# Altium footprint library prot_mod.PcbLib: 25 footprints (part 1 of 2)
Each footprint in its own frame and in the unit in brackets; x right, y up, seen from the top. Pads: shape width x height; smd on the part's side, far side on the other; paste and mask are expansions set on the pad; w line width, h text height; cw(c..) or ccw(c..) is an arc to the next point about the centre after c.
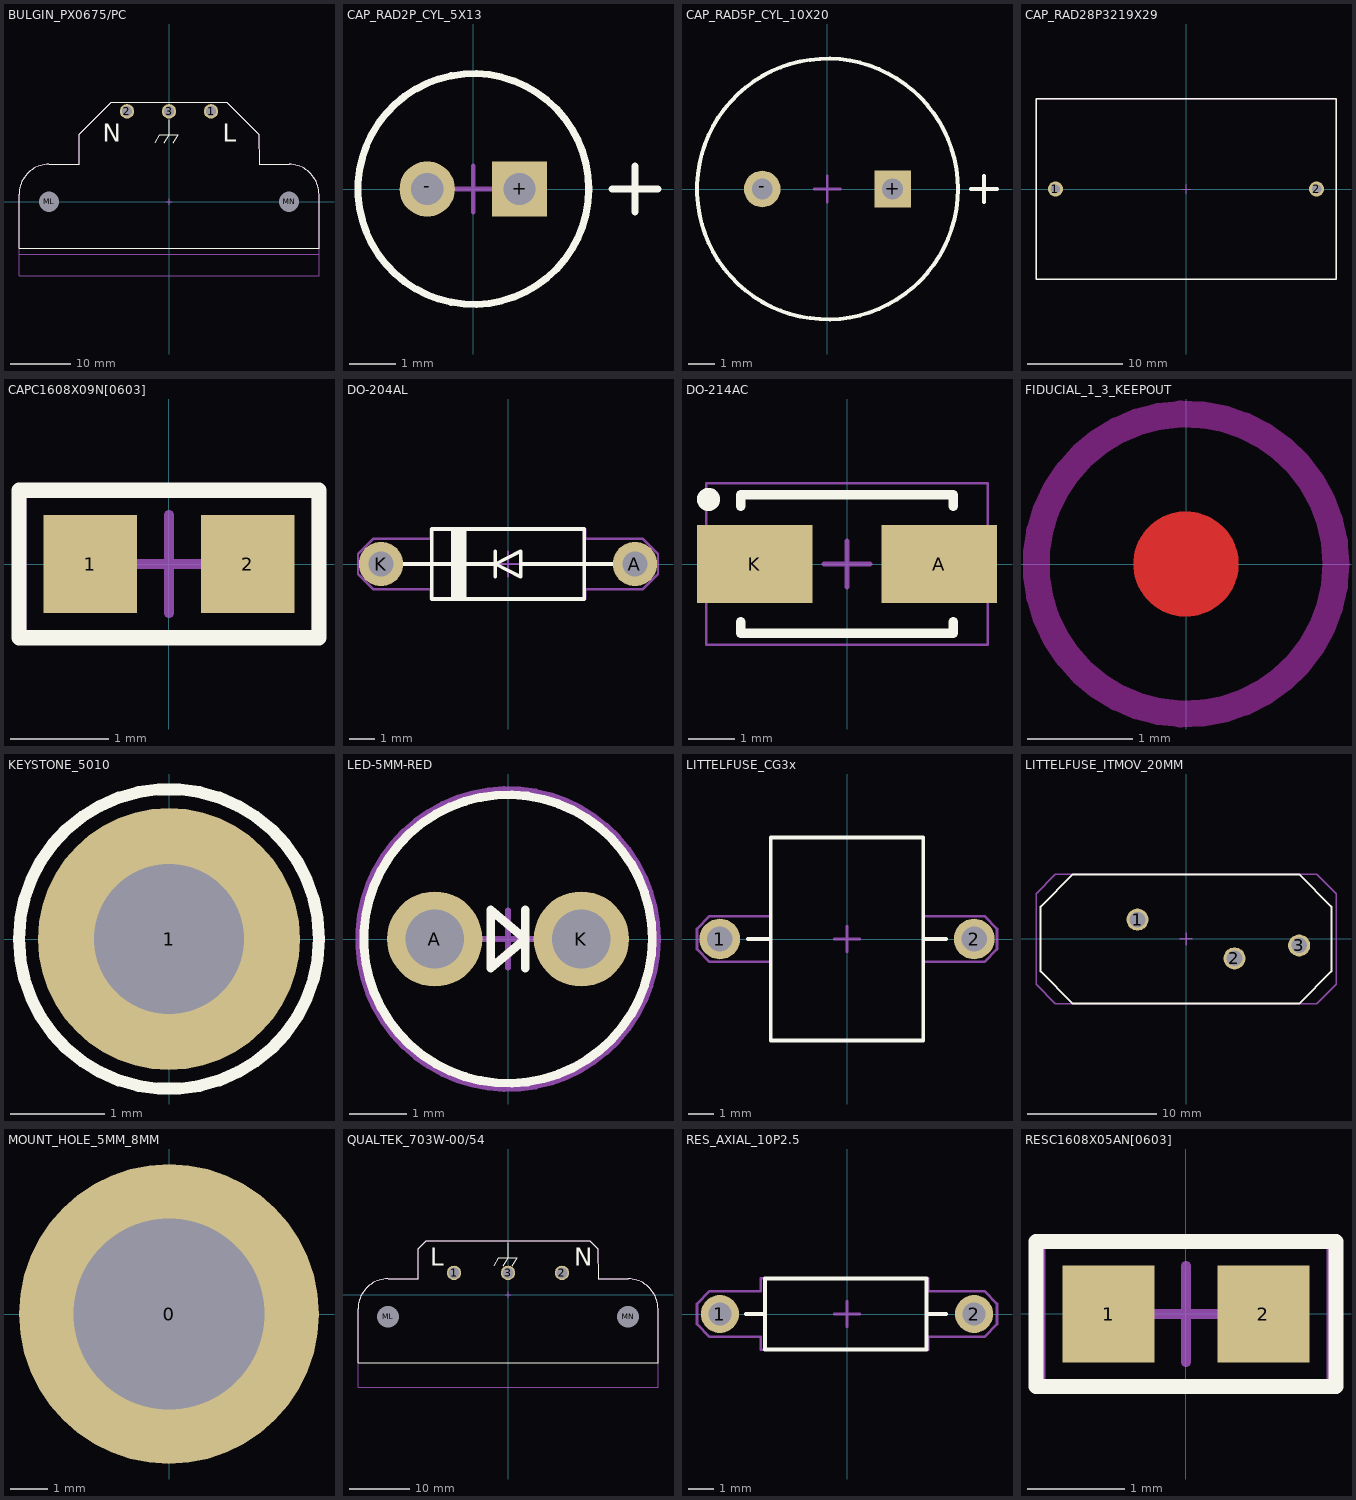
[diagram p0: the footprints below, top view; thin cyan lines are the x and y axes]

## BULGIN_PX0675/PC [mm]
pads (5):
  round 2.4 hole 1.7: 1(7,15.1) 2(-7,15.1) 3(0,15.1)
  round 2 hole 3.4 unplated: ML(-20,0) MN(20,0)
Top Overlay:
  lines w0.153: -2.306,9.853 -1.508,11.15 0,11.15 ; -0.8,9.85 0,11.15 ; 0,13.65 0,11.15 ; 0.722,9.836 1.531,11.15 0,11.15 ; -25,-7.75 25,-7.75 25,1.25 ccw(c20,1.25) 20,6.25 15,6.25 15,11.25 9.65,16.6 -9.65,16.6 -15,11.25 -15,6.25 -20,6.25 ccw(c-20,1.25) -25,1.25 -25,-7.75
  text "N" at -11,10 h3
  text "L" at 9,10 h3
Top Component Center:
  lines w0.1: -0.5,0 0.5,0 ; 0,-0.5 0,0.5
Top Courtyard:
  lines w0.1: -25,-12.3 25,-12.3 25,1.25 ccw(c20,1.25) 20,6.25 15,6.25 15,11.25 9.65,16.6 -9.65,16.6 -15,11.25 -15,6.25 -20,6.25 ccw(c-20,1.25) -25,1.25 -25,-12.3
  lines w0.127: -25,-8.7 25,-8.7
3D body "px0675-pc.stp": height 30.2, standoff -3.8, extent -24.936,-12.251 24.864,25.786

## CAP_RAD2P_CYL_5X13 [mm]
pads (2):
  rect 1.2x1.2 hole 0.7: +(1,0)
  round 1.2 hole 0.7: -(-1,0)
Top Overlay:
  circle w0.153: c0,0 r2.5
  lines w0.153: 3,0 4,0 ; 3.5,-0.5 3.5,0.5
Top Component Center:
  lines w0.1: -0.5,0 0.5,0 ; 0,-0.5 0,0.5
Top Courtyard:
  circle w0.1: c0,0 r2.5
3D body "Kemet_RB2x5x12_5_ESH226M035AC3AA.step": height 12.5, standoff -5, extent -2.745,-2.75 2.745,2.75

## CAP_RAD5P_CYL_10X20 [mm]
pads (2):
  rect 1.4x1.4 hole 0.8: +(2.5,0)
  round 1.4 hole 0.8: -(-2.5,0)
Top Overlay:
  circle w0.153: c0,0 r5
  lines w0.153: 5.5,0 6.5,0 ; 6,-0.5 6,0.5
Top Component Center:
  lines w0.1: -0.5,0 0.5,0 ; 0,-0.5 0,0.5
Top Courtyard:
  circle w0.1: c0,0 r5
3D body "Kemet_ESH687M035AH4AA.step": height 22, standoff -5, extent -5.25,-5.225 5.25,5.275

## CAP_RAD28P3219X29 [mm]
pads (2):
  round 1.6 hole 1: 1(-13.75,0) 2(13.75,0)
Top Overlay:
  lines w0.153: -15.8,-9.5 15.8,-9.5 15.8,9.5 -15.8,9.5 -15.8,-9.5
Top Component Center:
  lines w0.1: -0.5,0 0.5,0 ; 0,-0.5 0,0.5
Top Courtyard:
  lines w0.1: -15.8,-9.5 -15.8,9.5 15.8,9.5 15.8,-9.5 -15.8,-9.5
3D body "Kemet_PHE845VF6330MR06L2.step": height 29.05, standoff -4.95, extent -15.75,-9.501 15.75,9.5

## CAPC1608X09N[0603] [mm]
pads (2):
  rect 0.95x1 smd: 1(-0.8,0) 2(0.8,0)
Top Overlay:
  lines w0.153: -1.525,-0.75 1.525,-0.75 1.525,0.75 -1.525,0.75 -1.525,0 -1.525,-0.75
Top Component Center:
  lines w0.1: -0.5,0 0.5,0 ; 0,-0.5 0,0.5
Top Courtyard:
  lines w0.1: -1.5,-0.75 -1.5,0.75 1.5,0.75 1.5,-0.75 -1.5,-0.75
3D body: height 0.9, standoff 0, extent -0.55,-0.45 0.55,0.45
3D body: height 0.9, standoff 0, extent -0.85,-0.45 -0.55,0.45
3D body: height 0.9, standoff 0, extent 0.55,-0.45 0.85,0.45

## DO-204AL [mil]
pads (2):
  round 70 hole 40: A(200,0) K(-200,0)
Top Overlay:
  region: -64.97,55.11 -89.97,55.11 -89.97,-54.89 -64.97,-54.89
  lines w6.02: -165,0 -135,0 -80,0 -20,0 ; -20,-20 -20,20 ; 20,0 120,0 ; 135,0 165,0 ; 140,0 120,0 ; -20,0 20,20 20,-20 -20,0 ; 120,0 120,55 -120,55 -120,0 -120,-55 120,-55 120,0
Top Component Center:
  lines w3.94: -19.68,0 19.68,0 ; 0,-19.68 0,19.68
Top Courtyard:
  lines w3.94: -236.22,-15.75 -236.22,0 -236.22,15.75 -212.6,39.37 -122.05,39.37 -122.05,55.12 122.05,55.12 122.05,39.37 212.6,39.37 236.22,15.75 236.22,-15.75 212.6,-39.37 122.05,-39.37 122.05,-55.12 -122.05,-55.12 -122.05,-39.37 -212.6,-39.37 -236.22,-15.75
3D body: height 60, standoff -100, extent 184.06,-15.03 214.06,14.97
3D body: height 75, standoff 45, extent 184.16,-15 214.16,15
3D body: height 75, standoff 45, extent -215.92,-15.06 -185.92,14.94
3D body: height 60, standoff -100, extent -215.94,-15.03 -185.94,14.97
3D body: height 116, standoff 4, extent -94,-56.11 -54,55.89
3D body: height 75, standoff 45, extent -200,-14.97 200,15.03
3D body: height 115, standoff 5, extent -119,-55.11 121,54.89

## DO-214AC [mm]
pads (2):
  rect 2.5x1.7 smd: A(2,0) K(-2,0)
Top Overlay:
  circle w0.25: c-3,1.4 r0.125
  lines w0.2: -2.3,-1.25 -2.3,-1.5 2.3,-1.5 2.3,-1.25 ; -2.3,1.25 -2.3,1.5 2.3,1.5 2.3,1.25
Top Component Center:
  lines w0.1: -0.5,0 0.5,0 ; 0,-0.5 0,0.5
Top Courtyard:
  lines w0.05: -3.05,-1.75 3.05,-1.75 3.05,1.75 -3.05,1.75 -3.05,-1.75
3D body: height 2.4, standoff 0, extent -2.3,-1.46 2.3,1.46
3D body: height 2.4, standoff 2.4, extent -2.3,-1.45 -1.675,1.45

## FIDUCIAL_1_3_KEEPOUT [mm]
Top Layer:
  circle w0.5: c0,0 r0.25
Top Layer keep-out:
  circle w0.254: c0,0 r1.425
Top Solder:
  circle w1.5: c0,0 r0.75

## KEYSTONE_5010 [mil]
pads (1):
  round 110 / inner round 85 / far side round 110 hole 63: 1(0,0)
Top Overlay:
  circle w5: c0,0 r62.99
Top Component Center:
  lines w3.94: -19.68,0 19.68,0 ; 0,-19.68 0,19.68
Top Courtyard:
  circle w3.94: c0,0 r62.99
3D body "keystone-PN5010.STEP": height 319.63, standoff -125, extent -62.05,-62.01 62.04,62.99

## LED-5MM-RED [mil]
pads (2):
  round 65 hole 40: A(-50,0) K(50,0)
Top Overlay:
  circle w6.02: c0,0 r98.43
  lines w6.02: 11.81,-19.68 11.81,19.68 ; -11.81,-19.68 -11.81,19.68 11.81,0 -11.81,-19.68
Top Component Center:
  lines w3.94: -19.68,0 19.68,0 ; 0,-19.68 0,19.68
Top Courtyard:
  circle w3.94: c0,0 r102.36
3D body: height 110, standoff 70, extent -105,-105.21 105,104.79
3D body: height 370, standoff 170, extent -100.04,-100.43 99.96,99.57
3D body: height 270, standoff 70, extent -99.79,-100.2 100.21,99.8
3D body: height 170, standoff 160, extent -5,-5 5,5
3D body: height 160, standoff 150, extent -29,-7 -20,7
3D body: height 60, standoff -120, extent -62.5,-13 -37.5,12
3D body: height 160, standoff 150, extent -15,-33 40,33
3D body: height 150, standoff 50, extent 19,-12.5 62,12.5
3D body: height 150, standoff 50, extent -63,-13 -20,12
3D body: height 50, standoff -120, extent 37,-12.5 62,12.5

## LITTELFUSE_CG3x [mm]
pads (2):
  round 1.6 hole 1: 1(-5,0) 2(5,0)
Top Overlay:
  lines w0.153: -3.9,0 -3,0 ; 3,0 3.9,0 ; -3,0 -3,1.925 -3,4 3,4 3,-4 -3,-4 -3,0
Top Component Center:
  lines w0.1: -0.5,0 0.5,0 ; 0,-0.5 0,0.5
Top Courtyard:
  lines w0.1: -5.9,-0.4 -5.4,-0.9 -3,-0.9 -3,-4 3,-4 3,-0.9 5.4,-0.9 5.9,-0.4 5.9,0.4 5.4,0.9 3,0.9 3,4 -3,4 -3,0.9 -5.4,0.9 -5.9,0.4 -5.9,-0.4
3D body: height 8, standoff 0, extent -2.6,-4 2.6,4
3D body: height 8, standoff 0, extent -3,-4 -2.6,4
3D body: height 8, standoff 0, extent 2.6,-4 3,4
3D body: height 4.4, standoff 3.6, extent -5.2,-0.401 -3,0.399
3D body: height 4.4, standoff 3.6, extent 3,-0.4 5.2,0.4
3D body: height 4.2, standoff -2, extent -5.403,-0.4 -4.603,0.4
3D body: height 4.2, standoff -2, extent 4.6,-0.4 5.4,0.4

## LITTELFUSE_ITMOV_20MM [mm]
pads (3):
  round 1.7 hole 1.2: 1(-3.75,1.5) 2(3.75,-1.5) 3(8.75,-0.5)
Top Overlay:
  lines w0.153: -11.25,-2.5 -8.75,-5 8.75,-5 11.25,-2.5 11.25,2.5 8.75,5 -8.75,5 -11.25,2.5 -11.25,-2.5
Top Component Center:
  lines w0.1: -0.5,0 0.5,0 ; 0,-0.5 0,0.5
Top Courtyard:
  lines w0.1: -11.6,-3.5 -11.6,3.5 -10.1,5 10.1,5 11.6,3.5 11.6,-3.5 10.1,-5 -10.1,-5 -11.6,-3.5
3D body: height 0, standoff -2, extent 8.52,-0.73 8.98,-0.27
3D body: height 0, standoff -2, extent 3.52,-1.73 3.98,-1.27
3D body: height 0, standoff -2, extent -3.98,1.27 -3.52,1.73
3D body: height 9, standoff 0, extent 8.15,-1.1 9.35,0.1
3D body: height 6, standoff 0, extent 3.15,-2.1 4.35,-0.9
3D body: height 6, standoff 0, extent -4.35,0.9 -3.15,2.1
3D body: height 27.5, standoff 4.5, extent -11.5,-3.5 11.5,3.5

## MOUNT_HOLE_5MM_8MM [mm]
pads (1):
  round 8 hole 5.08: 0(0,0)

## QUALTEK_703W-00/54 [mm]
pads (5):
  round 2.4 hole 1.8: 1(-9,3.65) 2(9,3.65) 3(0,3.65)
  round 2 hole 3.6 unplated: ML(-20,-3.65) MN(20,-3.65)
Top Overlay:
  lines w0.153: -2.306,4.853 -1.508,6.15 0,6.15 ; -0.8,4.85 0,6.15 ; 0,8.65 0,6.15 ; 0.722,4.836 1.531,6.15 0,6.15 ; -25,-11.35 -25,-2.35 cw(c-20,-2.35) -20,2.65 -15,2.65 -15,7.65 -13.65,9 13.65,9 15,7.65 15,2.65 20,2.65 cw(c20,-2.35) 25,-2.35 25,-11.35 -25,-11.35
  text "L" at -13,4.85 h3
  text "N" at 11,4.85 h3
Top Component Center:
  lines w0.1: -0.5,0 0.5,0 ; 0,-0.5 0,0.5
Top Courtyard:
  lines w0.1: -25,-15.4 -25,-2.35 cw(c-20,-2.35) -20,2.65 -15,2.65 -15,7.65 -13.65,9 13.65,9 15,7.65 15,2.65 20,2.65 cw(c20,-2.35) 25,-2.35 25,-15.4 -25,-15.4
3D body "703w0054.STEP": height 28.1, standoff -3.62, extent -25.002,-15.366 24.998,8.434

## RES_AXIAL_10P2.5 [mm]
pads (2):
  round 1.5 hole 0.9: 1(-5,0) 2(5,0)
Top Overlay:
  lines w0.153: -3.984,0 -3.222,0 ; 3.128,0 3.89,0 ; -3.222,-1.4 -3.222,1.4 3.128,1.4 3.128,-1.4 -3.222,-1.4
Top Component Center:
  lines w0.1: -0.5,0 0.5,0 ; 0,-0.5 0,0.5
Top Courtyard:
  lines w0.1: -5.9,-0.4 -5.4,-0.9 -3.4,-0.9 -3.4,-1.4 3.2,-1.4 3.2,-0.9 5.4,-0.9 5.9,-0.4 5.9,0 5.9,0.4 5.4,0.9 3.2,0.9 3.2,1.4 -3.4,1.4 -3.4,0.9 -5.4,0.9 -5.9,0.4 -5.9,0 -5.9,-0.4
3D body: height 2.35, standoff 0.15, extent -2.25,-1.1 2.25,1.1
3D body: height 2.5, standoff 0, extent 2.25,-1.25 3.25,1.25
3D body: height 1.4, standoff -2, extent 4.7,-0.3 5.3,0.3
3D body: height 1.4, standoff -2, extent -5.3,-0.3 -4.7,0.3
3D body: height 1.55, standoff 0.95, extent 4,-0.3 5.15,0.3
3D body: height 1.55, standoff 0.95, extent -5.15,-0.3 -4,0.3
3D body: height 1.75, standoff 0.75, extent 3.25,-0.5 4,0.5
3D body: height 1.75, standoff 0.75, extent -4,-0.5 -3.25,0.5
3D body: height 2.5, standoff 0, extent -3.25,-1.25 -2.25,1.25

## RESC1608X05AN[0603] [mm]
pads (2):
  rect 0.95x1 smd: 1(-0.8,0) 2(0.8,0)
Top Overlay:
  lines w0.153: -1.55,-0.75 1.55,-0.75 1.55,0.75 -1.55,0.75 -1.55,-0.75
Top Component Center:
  lines w0.1: -0.5,0 0.5,0 ; 0,-0.5 0,0.5
Top Courtyard:
  lines w0.1: -1.5,-0.75 1.5,-0.75 1.5,0.75 -1.5,0.75 -1.5,-0.75
3D body "RESC1608X55.STEP": height 0.55, standoff 0, extent -0.8,-0.4 0.8,0.4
